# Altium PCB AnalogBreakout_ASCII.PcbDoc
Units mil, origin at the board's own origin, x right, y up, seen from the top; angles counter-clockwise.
Board outline 1000 x 3095 mil, 2 copper layers (Top Layer, Bottom Layer); 31 components, 26 nets, 117 pads, 10 vias.
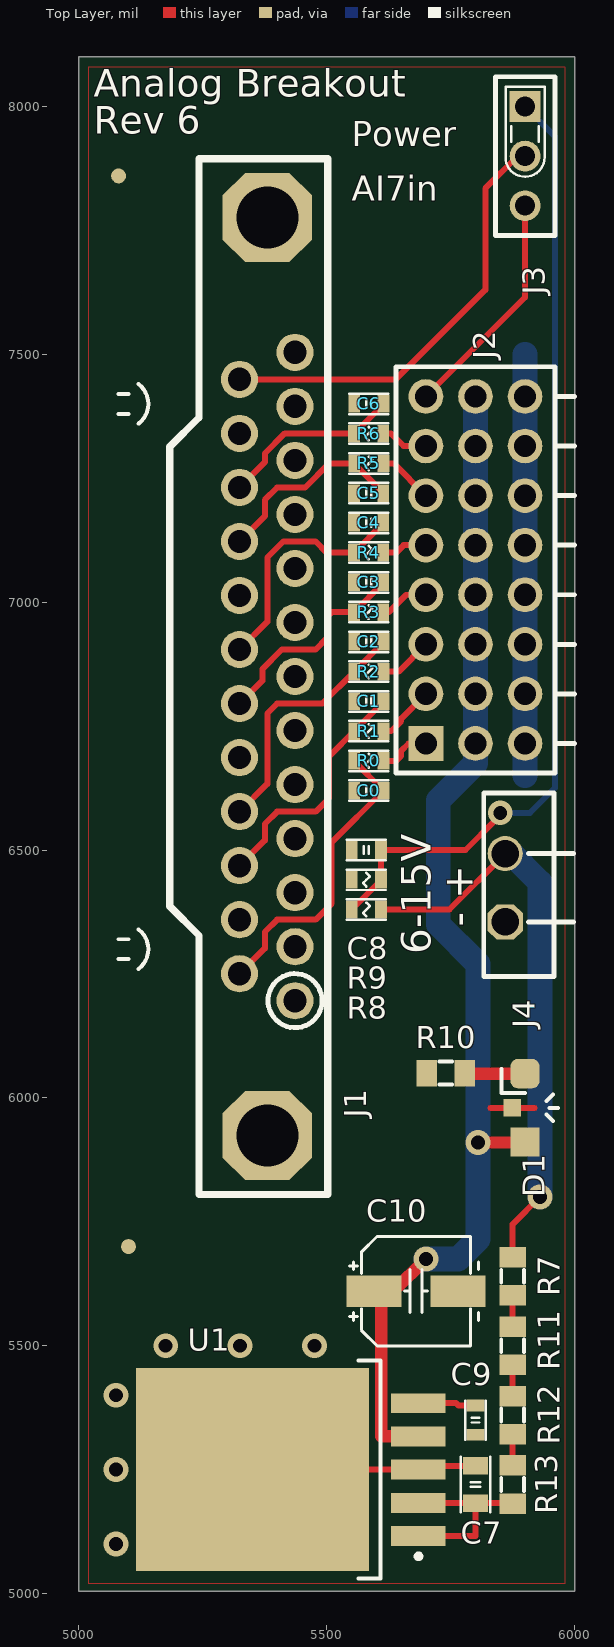
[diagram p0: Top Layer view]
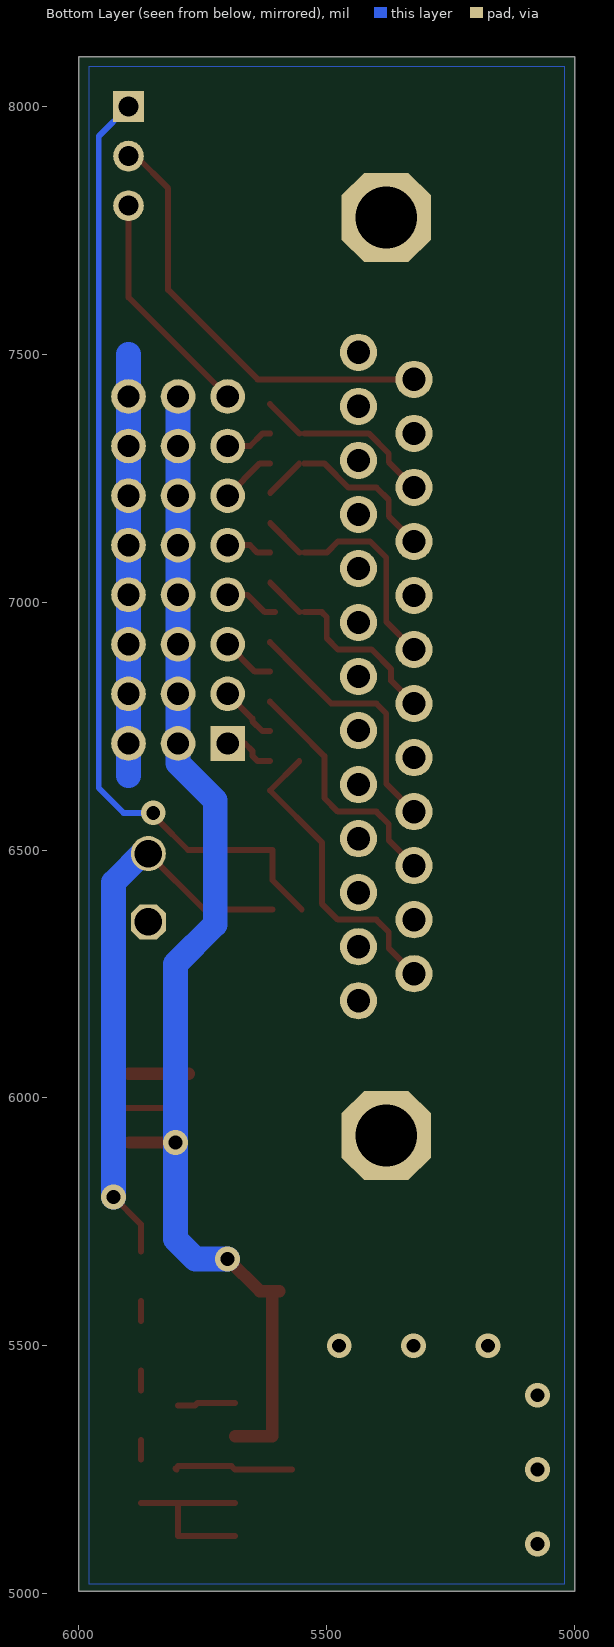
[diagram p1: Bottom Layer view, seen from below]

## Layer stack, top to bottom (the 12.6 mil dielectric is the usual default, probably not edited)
Top Layer: signal copper 1.4
Dielectric: dielectric 12.6, FR-4, Dk 4.8
Bottom Layer: signal copper 1.4

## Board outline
5000,8100 6000,8100 6000,5005 5000,5005

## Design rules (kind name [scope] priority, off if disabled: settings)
Clearance [All] p0: scope1count=1 scope1_0_kind=Board scope1_0_value=Board scope2count=1 scope2_0_kind=Board scope2_0_value=Board commentlength=0 gap=7
Clearance [All] p1: gap=7
ComponentClearance [All] p0: scope1count=1 scope1_0_kind=Board scope1_0_value=Board scope2count=1 scope2_0_kind=Board scope2_0_value=Board commentlength=0 gap=20 collisioncheckmode=3
ComponentClearance [All] p1: gap=20 collisioncheckmode=3 verticalgap=10 showdistances=FALSE
DiffPairsRouting [All] p0: scope1count=1 scope1_0_kind=Board scope1_0_value=Board scope2count=1 scope2_0_kind=Board scope2_0_value=Board commentlength=0
FanoutControl Fanout_BGA [All] p0 off: scope1count=1 scope1_0_kind=Board scope1_0_value=Board scope2count=1 scope2_0_kind=Board scope2_0_value=Board commentlength=69 // Protel DXP Scope 1 Expression Was: IsBGA   Fanout_BGA (Default Rule)
FanoutControl Fanout_LCC [All] p0 off: scope1count=1 scope1_0_kind=Board scope1_0_value=Board scope2count=1 scope2_0_kind=Board scope2_0_value=Board commentlength=69 // Protel DXP Scope 1 Expression Was: IsLCC   Fanout_LCC (Default Rule)
FanoutControl Fanout_SOIC [All] p0 off: scope1count=1 scope1_0_kind=Board scope1_0_value=Board scope2count=1 scope2_0_kind=Board scope2_0_value=Board commentlength=71 // Protel DXP Scope 1 Expression Was: IsSOIC   Fanout_SOIC (Default Rule)
FanoutControl Fanout_Small [All] p0 off: scope1count=1 scope1_0_kind=Board scope1_0_value=Board scope2count=1 scope2_0_kind=Board scope2_0_value=Board commentlength=84 // Protel DXP Scope 1 Expression Was: (CompPinCount < 5)   Fanout_Small (Default Rule)
FanoutControl Fanout_Default [All] p0: scope1count=1 scope1_0_kind=Board scope1_0_value=Board scope2count=1 scope2_0_kind=Board scope2_0_value=Board commentlength=30 // Fanout_Default (Default Rule)
Height [All] p0: scope1count=1 scope1_0_kind=Board scope1_0_value=Board scope2count=1 scope2_0_kind=Board scope2_0_value=Board commentlength=0
HoleSize [All] p0: scope1count=1 scope1_0_kind=Board scope1_0_value=Board scope2count=1 scope2_0_kind=Board scope2_0_value=Board commentlength=0 absolutevalues=TRUE maxlimit=150 minlimit=1 maxpercent=80.000 minpercent=20.000
HoleSize [All] p1: absolutevalues=TRUE maxlimit=150 minlimit=1 maxpercent=80.000 minpercent=20.000
LayerPairs [All] p0: scope1count=1 scope1_0_kind=Board scope1_0_value=Board scope2count=1 scope2_0_kind=Board scope2_0_value=Board commentlength=0 enforce=TRUE
PasteMaskExpansion [All] p0: scope1count=1 scope1_0_kind=Board scope1_0_value=Board scope2count=1 scope2_0_kind=Board scope2_0_value=Board commentlength=0 expansion=0
PlaneClearance [All] p0: scope1count=1 scope1_0_kind=Board scope1_0_value=Board scope2count=1 scope2_0_kind=Board scope2_0_value=Board commentlength=0 clearance=20
PlaneConnect [All] p0: scope1count=1 scope1_0_kind=Board scope1_0_value=Board scope2count=1 scope2_0_kind=Board scope2_0_value=Board commentlength=0 planeconnectstyle=Relief reliefexpansion=20 reliefentries=4 reliefconductorwidth=10 reliefairgap=10
PolygonConnect PolygonConnect_2 [All] p0 off: scope1count=1 scope1_0_kind=Board scope1_0_value=Board scope2count=1 scope2_0_kind=Board scope2_0_value=Board commentlength=46 connectstyle=Direct reliefconductorwidth=10 reliefentries=4 polygonreliefangle="90 Angle" // Protel DXP Scope 1 Expression Was: (IsVia)
PolygonConnect PolygonConnect_1 [All] p0 off: scope1count=1 scope1_0_kind=Board scope1_0_value=Board scope2count=1 scope2_0_kind=Board scope2_0_value=Board commentlength=58 connectstyle=Direct reliefconductorwidth=10 reliefentries=4 polygonreliefangle="90 Angle" // Protel DXP Scope 1 Expression Was: (InComponent('U1'))
PolygonConnect [All] p0: scope1count=1 scope1_0_kind=Board scope1_0_value=Board scope2count=1 scope2_0_kind=Board scope2_0_value=Board commentlength=0 connectstyle=Relief reliefconductorwidth=10 reliefentries=4 polygonreliefangle="90 Angle"
PolygonConnect PolygonConnect_2 [(IsVia)] p1: connectstyle=Direct reliefconductorwidth=10 reliefentries=4 polygonreliefangle="90 Angle"
PolygonConnect PolygonConnect_1 [(InComponent('U1'))] p2: connectstyle=Direct reliefconductorwidth=10 reliefentries=4 polygonreliefangle="90 Angle"
PolygonConnect [All] p3: connectstyle=Relief reliefconductorwidth=10 reliefentries=4 polygonreliefangle="90 Angle"
RoutingCorners [All] p0: scope1count=1 scope1_0_kind=Board scope1_0_value=Board scope2count=1 scope2_0_kind=Board scope2_0_value=Board commentlength=0 cornerstyle=45-Degree minsetback=100 maxsetback=100
RoutingLayers [All] p0: scope1count=1 scope1_0_kind=Board scope1_0_value=Board scope2count=1 scope2_0_kind=Board scope2_0_value=Board commentlength=0 top layer=Automatic bottom layer=Automatic
RoutingPriority [All] p0: scope1count=1 scope1_0_kind=Board scope1_0_value=Board scope2count=1 scope2_0_kind=Board scope2_0_value=Board commentlength=0
RoutingTopology [All] p0: scope1count=1 scope1_0_kind=Board scope1_0_value=Board scope2count=1 scope2_0_kind=Board scope2_0_value=Board commentlength=0 topology=Shortest
RoutingVias [All] p0: scope1count=1 scope1_0_kind=Board scope1_0_value=Board scope2count=1 scope2_0_kind=Board scope2_0_value=Board commentlength=0 holewidth=28 width=50 viastyle="Through Hole" minholewidth=28 minwidth=50 maxholewidth=50 maxwidth=80
RoutingVias [All] p1: holewidth=28 width=50 viastyle="Through Hole" minholewidth=28 minwidth=50 maxholewidth=50 maxwidth=80
ShortCircuit [All] p0: scope1count=1 scope1_0_kind=Board scope1_0_value=Board scope2count=1 scope2_0_kind=Board scope2_0_value=Board commentlength=0 allowed=FALSE
SolderMaskExpansion [All] p0: scope1count=1 scope1_0_kind=Board scope1_0_value=Board scope2count=1 scope2_0_kind=Board scope2_0_value=Board commentlength=0 expansion=4
SolderMaskExpansion [All] p1: expansion=4
TestPointUsage [All] p0: scope1count=1 scope1_0_kind=Board scope1_0_value=Board scope2count=1 scope2_0_kind=Board scope2_0_value=Board commentlength=0 valid=0 allowmultiple=FALSE
TestPointUsage [All] p1: valid=0 allowmultiple=FALSE
Testpoint [All] p0: scope1count=1 scope1_0_kind=Board scope1_0_value=Board scope2count=1 scope2_0_kind=Board scope2_0_value=Board commentlength=0 side=15 testpointundercomponent=TRUE minsize=40 maxsize=100 preferedsize=60 minholesize=0 maxholesize=40 preferedholesize=32 testpointgrid=1 style=1023 order=0123456789
Testpoint [All] p1: side=15 testpointundercomponent=TRUE minsize=40 maxsize=100 preferedsize=60 minholesize=0 maxholesize=40 preferedholesize=32 testpointgrid=1 style=1023 order=0123456789
UnRoutedNet [All] p0: scope1count=1 scope1_0_kind=Board scope1_0_value=Board scope2count=1 scope2_0_kind=Board scope2_0_value=Board commentlength=0
Width [All] p0: scope1count=1 scope1_0_kind=Board scope1_0_value=Board scope2count=1 scope2_0_kind=Board scope2_0_value=Board commentlength=0 maxlimit=100 minlimit=10 preferedwidth=10
Width [All] p1: maxlimit=100 minlimit=10 preferedwidth=10
17 further rules are at their usual default settings.

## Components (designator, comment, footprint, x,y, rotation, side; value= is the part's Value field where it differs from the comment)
C0 "1.0 uF 0603" C0603_C 5585,6620 r0 top
C1 "1.0 uF 0603" C0603_C 5585,6800 r0 top
C2 "1.0 uF 0603" C0603_C 5585,6920 r0 top
C3 "1.0 uF 0603" C0603_C 5584.53,7040 r0 top
C4 "1.0 uF 0603" C0603_C 5584.53,7160 r0 top
C5 "1.0 uF 0603" C0603_C 5584.53,7220 r0 top
C6 "1.0 uF 0603" C0603_C 5585,7400 r180 top
C7 "4.7uF 0805 25V X5R" C0805_C 5800,5220 r270 top
C8 "1.0 uF 0603" C0603_C 5580,6500 r0 top
C9 "1000 pF 0603" C0603_C 5800,5350 r90 top
C10 "22uF SMT 25V Elecrolytic" "SMT-CAN Panasonic C" 5680,5610 r90 top
D1 "LTST-S320GKT" "LED1208RA LITEON" 5900,5980 r0 top
J1 "DB25 Right Angle" "DB25 - RA" 5380,6850 r270 top
J2 "PWM_Header x8 RA" H100P3x8RA 5700,6715 r90 top
J3 "Jumper" J100P3 5900,8000 r270 top
J4 "3.5mm Mini Header RA" "WAGO 734-162" 5860,6355 r90 top
R0 "100 ohm 0603 1%" R0603_C 5585,6680 r0 top
R1 "100 ohm 0603 1%" R0603_C 5585,6740 r0 top
R2 "100 ohm 0603 1%" R0603_C 5585,6860 r0 top
R3 "100 ohm 0603 1%" R0603_C 5584.53,6980 r0 top
R4 "100 ohm 0603 1%" R0603_C 5584.53,7100 r0 top
R5 "100 ohm 0603 1%" R0603_C 5585,7280 r0 top
R6 "100 ohm 0603 1%" R0603_C 5584.53,7340 r0 top
R7 "1.00 ohm 0805 1%" R0805_M 5875,5640 r270 top
R8 "680 ohm 0805 1%" R0603_C 5580,6380 r0 top
R9 "1.0k ohm 0603 1%" R0603_C 5580,6440 r0 top
R10 "150 ohm 0805 1%" R0805_M 5740,6050 r0 top
R11 "1.00 ohm 0805 1%" R0805_M 5875,5500 r270 top
R12 "1.00 ohm 0805 1%" R0805_M 5875,5360 r270 top
R13 "1.00 ohm 0805 1%" R0805_M 5875,5220 r270 top
U1 "MIC5209-5.0BU" TO-263-5 5485,5250 r90 top

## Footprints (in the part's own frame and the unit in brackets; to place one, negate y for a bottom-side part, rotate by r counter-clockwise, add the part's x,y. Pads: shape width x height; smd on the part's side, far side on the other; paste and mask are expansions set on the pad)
C0603_C [mm]
  rect 0.6x0.9 smd: 1(-0.75,0) 2(0.75,0)
  silkscreen extent -1,-0.53 1,0.53
C0805_C [mm]
  rect 0.9x1.3 smd: 1(-0.95,0) 2(0.95,0)
  silkscreen extent -1.43,-0.76 1.43,0.76
"DB25 - RA" [mil]
  round 75 hole 47: 1(654.02,55.98) 2(545,56) 3(436,56) 4(327,56) 5(218,56) 6(109,56) 7(0,56) 8(-109,56) 9(-218,56) 10(-327,56) 11(-436,56) 12(-545,56) 13(-654.02,55.98) 14(599.49,-55.98) 15(490.5,-56) 16(381.5,-56) 17(272.5,-56) 18(163.5,-56) 19(54.5,-56) 20(-54.5,-56) 21(-163.5,-56) 22(-272.5,-56) 23(-381.5,-56) 24(-490.5,-56) 25(-599.49,-55.98)
  oct 180x180 hole 125: SHELL(-925.98,0) SHELL(925.98,0)
  silkscreen extent -1045,-197 1045,122
H100P3x8RA [mil] "Header 100mil, 8X2POS THRU RA"
  rect 70x70 hole 45: 1(0,0)
  round 70 hole 45: 2(0,-100) 3(0,-200) 4(100,0) 5(100,-100) 6(100,-200) 7(200,0) 8(200,-100) 9(200,-200) 10(300,0) 11(300,-100) 12(300,-200) 13(400,0) 14(400,-100) 15(400,-200) 16(500,0) 17(500,-100) 18(500,-200) 19(600,0) 20(600,-100) 21(600,-200) 22(700,0) 23(700,-100) 24(700,-200)
  silkscreen extent -60,-300 760,60
J100P3 [mil] "Selection Jumper 100mil, 3POS THRU VERT"
  rect 62x62 hole 40.16: 1(0,0)
  round 62 hole 40.16: 2(100,0) 3(200,0)
  silkscreen extent -60,-60 260,60
"LED1208RA LITEON" [mm] "Lite ON Side Fire 1208 LED"
  rect 1.5x1.5 smd: A(0,-1.75)
  rrect50% 1.5x1.5 smd: K(0,1.75)
  rect 0.9x0.9 smd: ""(-0.65,0)
  silkscreen extent -1.2,-0.67 1.7,2
R0603_C [mm]
  rect 0.6x0.9 smd: 1(-0.75,0) 2(0.75,0)
  silkscreen extent -1,-0.53 1,0.53
R0805_M [mm] "Chip Resistor, 2-Leads, Body 2.0x1.3mm, IPC Medium Density"
  rect 1.05x1.35 smd: 1(-0.975,0) 2(0.975,0)
  silkscreen extent -0.33,-0.58 0.33,0.58
"SMT-CAN Panasonic C" [mm] "Panasonic SMT-CAN type Capacitor, Size code C"
  rect 1.6x2.8 smd: +(0,2.15) -(0,-2.15)
  silkscreen extent -2.8,-3.2 2.8,3.4
TO-263-5 [mil] "TO-263-5"
  rect 40x110 smd: 1(-134,-200) 2(-67,-200) 3(0,-200) 4(67,-200) 5(134,-200)
  rect 410x470 smd: PAD(0,135)
  silkscreen extent -220,-205 220,-79
"WAGO 734-162" [mm] "3.5mm 10 A Protected Header RA"
  oct 1.8x1.8 hole 1.4: 1(0,0)
  round 1.8 hole 1.4: 2(3.5,0)
  silkscreen extent -2.8,-3.5 6.6,1.1

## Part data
C0 C1 C2 C3 C4 C5 C6: library part "0.22 uF 0603 10V", "Capacitor"
C7: "CERAMIC 4.7uF 25V X5R 0805"
C8: library part "0.1uF 0805 Bypass", "Capacitor"
C9: library part "1.0µF 0603 10V", "Capacitor"
D1: "Green 1208RA 20mA 2V 10mcd"
J1: library part "DB25 Female RA", "D-SUB RCPT RA 25POS PCB AU"
J2: "PWM Header x8 RA"
J3: library part "Jumper 3pos 100mil", "Selection Jumper"
J4: library part "WAGO 734-162", "3.5mm Header Protected against Mismating"
R0 R1 R2 R3 R4 R5 R6: library part "1.0k ohm 0603 1%", "1.0k ohm 0603 1%"
R7: library part "3.9 ohm 0603 1%", "3.9 ohm 0603 1%"
R8 R9: library part "1.0k ohm 0805 1%", "1.0k ohm 0805 1%"
R10: library part "51 ohm 0805 1%", "51 ohm 0805 1%"
R11 R12 R13: library part "2.00 ohm 0805 1%", "2.00 ohm 0805 1%"
U1: "5.0V 500mA Low-Noise LDO"

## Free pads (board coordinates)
  round 30 smd: 0(5080,7860) 0(5100,5700)

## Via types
v1: diameter 50, hole 28, Top Layer to Bottom Layer, 10 vias

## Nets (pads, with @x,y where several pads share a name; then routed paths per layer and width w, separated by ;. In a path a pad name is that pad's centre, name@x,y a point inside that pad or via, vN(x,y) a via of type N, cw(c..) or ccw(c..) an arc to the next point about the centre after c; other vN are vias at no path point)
5V: C10.+ D1.A J2.2 J2.5 J2.8 J2.11 J2.14 J2.17 J2.20 J2.23 U1.4 | length 2592.4
  Top Layer w25: C10.+ C10.+@5610,5610 ; U1.4 5610,5317 C10.+@5610,5610 ; v1(5700,5675) 5635,5610 C10.+@5610,5610 ; v1(5805,5910) D1.A@5898.9,5910
  Bottom Layer w50: v1(5700,5675) 5765,5675 5805,5715 v1(5805,5910) 5805,6270 ; J2.23 J2.20 J2.17 J2.14 J2.11 J2.8 J2.5 J2.2 5800,6675 5725,6600 5725,6350 ; 5725,6350 5805,6270 ; 5725,6350 5805,6270
AGND: C0.1 C1.1 C2.1 C3.1 C4.1 C5.1 C6.2 C7.1 C8.1 C9.1 C10.- J1.1 J1.3 J1.4 J1.6 J1.7 J1.9 J1.10 J1.12 J1.13 J2.3 J2.6 J2.9 J2.12 J2.15 J2.18 J2.21 J2.24 J4.1 R9.1 R10.1 U1.3 U1.PAD | length 1086.5
  Top Layer w12: U1.PAD@5570,5250 U1.3 5692.4,5257.4 C7.1 ; C7.1@5802.6,5250 C7.1@5805,5252.4
  Bottom Layer w50: 5900,6650 J2.3 J2.6 J2.9 J2.12 J2.15 J2.18 J2.21 J2.24 5900,7500
  other v1: 5075,5100 5075,5250 5075,5400 5175,5500 5325,5500 5475,5500
AI7: J1.25 J3.2 | length 882.7
  Top Layer w12: J1.25 5639.49,7449.49 5820,7630 5820,7835 5885,7900 J3.2
ANALOGINPUT0: J2.1 R0.2 | length 106.3
  Top Layer w12: R0.2 5640,6680 5650,6690 5650,6700 5665,6715 J2.1 J2.1@5699.53,6715
ANALOGINPUT1: J2.4 R1.2 | length 119.5
  Top Layer w12: R1.2 5630,6740 5650,6760 5650,6765 J2.4
ANALOGINPUT2: J2.7 R2.2 | length 108.3
  Top Layer w12: R2.2 5645,6860 J2.7
ANALOGINPUT3: J2.10 R3.2 | length 110.4
  Top Layer w12: R3.2@5604.06,6980 R3.2 5625,6980 5660,7015 J2.10
ANALOGINPUT4: J2.13 R4.2 | length 92.2
  Top Layer w12: R4.2 5640,7100 5655,7115 J2.13
ANALOGINPUT5: J2.16 R5.2 | length 112.4
  Top Layer w12: R5.2 5635,7280 J2.16
ANALOGINPUT6: J2.19 R6.2 | length 96.3
  Top Layer w12: R6.2 5630,7340 5655,7315 J2.19
ANALOGINPUT7: J2.22 J3.3 | length 467.8
  Top Layer w12: J2.22 5900,7615 J3.3
NetC0_2: C0.2 J1.14 R0.1 | length 619.7
  Top Layer w12: J1.14 5375,6301.5 5375,6334.47 5400,6359.47 5477.53,6359.47 5510,6391.94 5510,6515.47 C0.2 5555.47,6679.06 R0.1
NetC1_2: C1.2 J1.16 R1.1 | length 497.3
  Top Layer w12: J1.16 5375,6519.5 5375,6552.47 5400,6577.47 5477.53,6577.47 5505,6604.94 5505,6689.53 R1.1 5614.53,6799.06 C1.2
NetC2_2: C2.2 J1.17 R2.1 | length 516.1
  Top Layer w12: J1.17 5380,6633.5 5380,6775.47 5400,6795.47 5490.94,6795.47 R2.1 5614.53,6919.06 C2.2
NetC3_2: C3.2 J1.19 R3.1 | length 420.9
  Top Layer w12: J1.19 5370,6841.5 5370,6865 5409.47,6904.47 5477.53,6904.47 5500,6926.94 5500,6970 5510,6980 R3.1@5545,6980 ; R3.1 5614.06,7039.06 C3.2
NetC4_2: C4.2 J1.20 R4.1 | length 480.9
  Top Layer w12: J1.20 5380,6960.5 5380,7090 5412.47,7122.47 5477.53,7122.47 5500,7100 R4.1@5545,7100 ; R4.1 5614.06,7159.06 C4.2
NetC5_2: C5.2 J1.22 R5.1 | length 390.3
  Top Layer w12: J1.22 5375,7173.5 5375,7206.47 5400,7231.47 5456.47,7231.47 5505,7280 R5.1@5545.47,7280 ; R5.1 5555.47,7279.53 5614.06,7220.94 C5.2
NetC6_1: C6.1 J1.23 R6.1 | length 361.2
  Top Layer w12: J1.23 5375,7282.5 5375,7300 5415.47,7340.47 5500,7340.47 5500.47,7340 R6.1@5545,7340 ; R6.1 5614.53,7399.53 C6.1
NetC7_2: C7.2 R13.2 U1.1 U1.2 | length 372
  Top Layer w12: U1.1 5800,5116 C7.2 ; U1.2 5685,5182.6 C7.2 ; R13.2@5875,5182.6 C7.2
NetC8_2: C8.2 J3.1 R8.1 R9.2 | length 1985.9
  Top Layer w12: R8.1 5609.53,6439.06 R9.2 C8.2 5780,6500 v1@5840,6560 ; J3.1@5881.61,8000 J3.1 ; v1@5840,6560 5850,6570 v1(5850,6575) v1@5840,6560
  Bottom Layer w12: v1(5850,6575) 5910,6575 5960,6625 5960,7940 J3.1
NetC9_2: C9.2 U1.5 | length 116.9
  Top Layer w12: U1.5 5761,5384 5765.47,5379.53 C9.2
NetD1_K: D1.K R10.2 | length 121.6
  Top Layer w25: R10.2@5778.39,6048.9 D1.K
NetR7_2: R7.2 R11.1 | length 40
  Top Layer w12: R11.1@5875,5550 R7.2@5875,5590
NetR11_2: R11.2 R12.1 | length 40
  Top Layer w12: R12.1@5875,5410 R11.2@5875,5450
NetR12_2: R12.2 R13.1 | length 40
  Top Layer w12: R13.1@5875,5270 R12.2@5875,5310
VBATT: J4.2 R7.1 R8.2 | length 1156.9
  Top Layer w12: R8.2 5747.2,6380 J4.2 ; R7.1@5875,5690 5875,5745 v1(5930,5800)
  Bottom Layer w50: J4.2@5865,6500 5866.1,6498.9 5930,6435 v1(5930,5800)
pads on no net: D1. J1.2 J1.5 J1.8 J1.11 J1.15 J1.18 J1.21 J1.24 J1.SHELL
copper on no net: | length 88.8
  Top Layer w12: 5830,5980 5874.41,5980 5918.82,5980

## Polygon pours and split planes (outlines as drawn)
AGND on Top Layer "GND" (solid, pour order 1000): 5020,8080 5980,8080 5980,5020 5020,5020 5020,8080
AGND on Bottom Layer "PWR" (solid, remove dead copper, pour order 1001): 5020,8080 5980,8080 5980,5020 5020,5020 5020,8080

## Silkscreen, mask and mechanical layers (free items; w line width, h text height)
Top Overlay:
  lines w8: 5080,6280 5100,6280 ; 5080,6320 5100,6320 ; 5080,7380 5100,7380 ; 5080,7420 5100,7420 ; 5120,6260 ccw(c5090,6300) 5120,6340 ; 5120,7360 ccw(c5090,7400) 5120,7440
  text "Analog Breakout" at 5030,8020 h55
  text "Rev 6" at 5030,7945 h55
  text "Power" at 5550,7920 h50
  text "AI7in" at 5550,7810 h50
  text "- +" at 5795,6345 h60 r90
  text "6-15V" at 5710,6290 h60 r90
Mechanical 1:
  lines w1.67: 7306.66,7663.72 11192.83,7663.72 ; 8941.72,6281.72 8941.72,7650.39
  lines w10: 5000,5005 6000,5005 6000,8100 5000,8100 5000,5005
  text "P" at 7651.32,8715.91 h148.77
  text "r" at 7743.01,8715.91 h148.77
  text "o" at 7789.69,8715.91 h148.77
  text "j" at 7866.37,8715.91 h148.77
  text "e" at 7898.05,8715.91 h148.77
  text "c" at 7974.73,8715.91 h148.77
  text "t" at 8044.75,8715.91 h148.77
  text "P" at 8843.48,8715.91 h148.77
  text "h" at 8935.17,8715.91 h148.77
  text "o" at 9011.85,8715.91 h148.77
  text "e" at 9088.54,8715.91 h148.77
  text "n" at 9165.23,8715.91 h148.77
  text "i" at 9241.91,8715.91 h148.77
  text "x" at 9271.92,8715.91 h148.77
  text "B" at 7651.32,8544.2 h148.77
  text "o" at 7743.01,8544.2 h148.77
  text "a" at 7819.7,8544.2 h148.77
  text "r" at 7896.38,8544.2 h148.77
  text "d" at 7943.06,8544.2 h148.77
  text "A" at 8843.48,8544.2 h148.77
  text "n" at 8935.17,8544.2 h148.77
  text "a" at 9011.85,8544.2 h148.77
  text "l" at 9088.54,8544.2 h148.77
  text "o" at 9118.55,8544.2 h148.77
  text "g" at 9195.23,8544.2 h148.77
  text "B" at 9310.26,8544.2 h148.77
  text "r" at 9401.95,8544.2 h148.77
  text "e" at 9448.63,8544.2 h148.77
  text "a" at 9525.31,8544.2 h148.77
  text "k" at 9602,8544.2 h148.77
  text "o" at 9673.68,8544.2 h148.77
  text "u" at 9750.37,8544.2 h148.77
  text "t" at 9827.05,8544.2 h148.77
  text "R" at 7651.32,8372.5 h148.77
  text "e" at 7751.35,8372.5 h148.77
  text "v" at 7828.03,8372.5 h148.77
  text "6" at 8843.48,8372.5 h148.77
  text "E" at 7651.32,8200.79 h148.77
  text "n" at 7743.01,8200.79 h148.77
  text "g" at 7819.7,8200.79 h148.77
  text "i" at 7896.38,8200.79 h148.77
  text "n" at 7926.39,8200.79 h148.77
  text "e" at 8003.07,8200.79 h148.77
  text "e" at 8079.76,8200.79 h148.77
  text "r" at 8156.44,8200.79 h148.77
  text "E" at 8843.48,8200.79 h148.77
  text "r" at 8935.17,8200.79 h148.77
  text "i" at 8981.85,8200.79 h148.77
  text "c" at 9011.85,8200.79 h148.77
  text "V" at 9120.21,8200.79 h148.77
  text "a" at 9211.9,8200.79 h148.77
  text "n" at 9288.59,8200.79 h148.77
  text "W" at 9365.27,8200.79 h148.77
  text "y" at 9503.64,8200.79 h148.77
  text "k" at 9568.66,8200.79 h148.77
  text "R" at 8843.48,8032.41 h148.77
  text "u" at 8943.5,8032.41 h148.77
  text "s" at 9020.19,8032.41 h148.77
  text "s" at 9090.21,8032.41 h148.77
  text "B" at 9198.57,8032.41 h148.77
  text "e" at 9290.26,8032.41 h148.77
  text "a" at 9366.94,8032.41 h148.77
  text "v" at 9443.63,8032.41 h148.77
  text "i" at 9511.98,8032.41 h148.77
  text "s" at 9541.98,8032.41 h148.77
  text "C" at 7333.3,7695.21 h148.77
  text "o" at 7433.33,7695.21 h148.77
  text "n" at 7510.01,7695.21 h148.77
  text "s" at 7586.7,7695.21 h148.77
  text "t" at 7656.71,7695.21 h148.77
  text "r" at 7695.06,7695.21 h148.77
  text "u" at 7741.73,7695.21 h148.77
  text "c" at 7818.42,7695.21 h148.77
  text "t" at 7888.44,7695.21 h148.77
  text "i" at 7926.78,7695.21 h148.77
  text "o" at 7956.79,7695.21 h148.77
  text "n" at 8033.47,7695.21 h148.77
  text "L" at 7333.3,7523.5 h148.77
  text "a" at 7409.99,7523.5 h148.77
  text "y" at 7486.67,7523.5 h148.77
  text "e" at 7551.69,7523.5 h148.77
  text "r" at 7628.37,7523.5 h148.77
  text "s" at 7675.05,7523.5 h148.77
  text "2" at 8975.02,7523.5 h148.77
  text "F" at 7333.3,7351.79 h148.77
  text "i" at 7418.32,7351.79 h148.77
  text "n" at 7448.33,7351.79 h148.77
  text "i" at 7525.01,7351.79 h148.77
  text "s" at 7555.02,7351.79 h148.77
  text "h" at 7625.04,7351.79 h148.77
  text "e" at 7701.72,7351.79 h148.77
  text "d" at 7778.41,7351.79 h148.77
  text "T" at 7893.44,7351.79 h148.77
  text "h" at 7980.13,7351.79 h148.77
  text "i" at 8056.81,7351.79 h148.77
  text "c" at 8086.82,7351.79 h148.77
  text "k" at 8156.84,7351.79 h148.77
  text "n" at 8228.52,7351.79 h148.77
  text "e" at 8305.21,7351.79 h148.77
  text "s" at 8381.89,7351.79 h148.77
  text "s" at 8451.91,7351.79 h148.77
  text "0" at 8975.02,7351.79 h148.77
  text "6" at 9051.7,7351.79 h148.77
  text "3" at 9128.39,7351.79 h148.77
  text "+" at 9243.42,7351.79 h148.77
  text "/" at 9323.44,7351.79 h148.77
  text "-" at 9361.78,7351.79 h148.77
  text "3" at 9446.8,7351.79 h148.77
  text "0" at 9523.48,7351.79 h148.77
  text "%" at 9600.17,7351.79 h148.77
  text "S" at 7333.3,7180.08 h148.77
  text "o" at 7424.99,7180.08 h148.77
  text "l" at 7501.68,7180.08 h148.77
  text "d" at 7531.68,7180.08 h148.77
  text "e" at 7608.37,7180.08 h148.77
  text "r" at 7685.05,7180.08 h148.77
  text "M" at 7770.07,7180.08 h148.77
  text "a" at 7885.1,7180.08 h148.77
  text "s" at 7961.79,7180.08 h148.77
  text "k" at 8031.81,7180.08 h148.77
  text "B" at 8975.02,7180.08 h148.77
  text "l" at 9066.71,7180.08 h148.77
  text "u" at 9096.71,7180.08 h148.77
  text "e" at 9173.4,7180.08 h148.77
  text "T" at 8975.02,7008.37 h148.77
  text "o" at 9061.7,7008.37 h148.77
  text "p" at 9138.39,7008.37 h148.77
  text "&" at 9253.42,7008.37 h148.77
  text "B" at 9383.45,7008.37 h148.77
  text "o" at 9475.14,7008.37 h148.77
  text "t" at 9551.83,7008.37 h148.77
  text "t" at 9590.17,7008.37 h148.77
  text "o" at 9628.51,7008.37 h148.77
  text "m" at 9705.2,7008.37 h148.77
  text "S" at 7333.3,6836.66 h148.77
  text "i" at 7424.99,6836.66 h148.77
  text "l" at 7455,6836.66 h148.77
  text "k" at 7485,6836.66 h148.77
  text "S" at 7595.03,6836.66 h148.77
  text "c" at 7686.72,6836.66 h148.77
  text "r" at 7756.74,6836.66 h148.77
  text "e" at 7803.42,6836.66 h148.77
  text "e" at 7880.1,6836.66 h148.77
  text "n" at 7956.79,6836.66 h148.77
  text "U" at 8975.02,6836.66 h148.77
  text "n" at 9075.04,6836.66 h148.77
  text "s" at 9151.73,6836.66 h148.77
  text "p" at 9221.74,6836.66 h148.77
  text "e" at 9298.43,6836.66 h148.77
  text "c" at 9375.11,6836.66 h148.77
  text "i" at 9445.13,6836.66 h148.77
  text "f" at 9475.14,6836.66 h148.77
  text "i" at 9515.15,6836.66 h148.77
  text "e" at 9545.16,6836.66 h148.77
  text "d" at 9621.84,6836.66 h148.77
  text "C" at 9736.87,6836.66 h148.77
  text "o" at 9836.9,6836.66 h148.77
  text "l" at 9913.58,6836.66 h148.77
  text "o" at 9943.59,6836.66 h148.77
  text "r" at 10020.27,6836.66 h148.77
  text "T" at 8975.02,6664.95 h148.77
  text "o" at 9061.7,6664.95 h148.77
  text "p" at 9138.39,6664.95 h148.77
  text "O" at 9253.42,6664.95 h148.77
  text "n" at 9361.78,6664.95 h148.77
  text "l" at 9438.46,6664.95 h148.77
  text "y" at 9468.47,6664.95 h148.77
  text "C" at 7333.3,6493.24 h148.77
  text "o" at 7433.33,6493.24 h148.77
  text "p" at 7510.01,6493.24 h148.77
  text "p" at 7586.7,6493.24 h148.77
  text "e" at 7663.38,6493.24 h148.77
  text "r" at 7740.07,6493.24 h148.77
  text "W" at 7825.09,6493.24 h148.77
  text "e" at 7963.46,6493.24 h148.77
  text "i" at 8040.14,6493.24 h148.77
  text "g" at 8070.15,6493.24 h148.77
  text "h" at 8146.83,6493.24 h148.77
  text "t" at 8223.52,6493.24 h148.77
  text "1" at 8975.02,6493.24 h148.77
  text "/" at 9051.7,6493.24 h148.77
  text "2" at 9090.04,6493.24 h148.77
  text "o" at 9205.07,6493.24 h148.77
  text "z" at 9281.76,6493.24 h148.77
  text "o" at 9386.78,6493.24 h148.77
  text "r" at 9463.47,6493.24 h148.77
  text "t" at 9548.49,6493.24 h148.77
  text "h" at 9586.83,6493.24 h148.77
  text "i" at 9663.52,6493.24 h148.77
  text "c" at 9693.53,6493.24 h148.77
  text "k" at 9763.54,6493.24 h148.77
  text "e" at 9835.23,6493.24 h148.77
  text "r" at 9911.91,6493.24 h148.77
  text "S" at 7333.3,6321.54 h148.77
  text "p" at 7424.99,6321.54 h148.77
  text "e" at 7501.68,6321.54 h148.77
  text "c" at 7578.36,6321.54 h148.77
  text "i" at 7648.38,6321.54 h148.77
  text "a" at 7678.39,6321.54 h148.77
  text "l" at 7755.07,6321.54 h148.77
  text "C" at 8975.02,6321.54 h148.77
  text "o" at 9075.04,6321.54 h148.77
  text "n" at 9151.73,6321.54 h148.77
  text "f" at 9228.41,6321.54 h148.77
  text "o" at 9268.42,6321.54 h148.77
  text "r" at 9345.11,6321.54 h148.77
  text "m" at 9391.79,6321.54 h148.77
  text "a" at 9510.15,6321.54 h148.77
  text "l" at 9586.83,6321.54 h148.77
  text "C" at 9655.18,6321.54 h148.77
  text "o" at 9755.21,6321.54 h148.77
  text "a" at 9831.89,6321.54 h148.77
  text "t" at 9908.58,6321.54 h148.77
  text "P" at 9985.26,6321.54 h148.77
  text "e" at 10076.95,6321.54 h148.77
  text "r" at 10153.64,6321.54 h148.77
  text "M" at 10238.66,6321.54 h148.77
  text "e" at 10353.69,6321.54 h148.77
  text "c" at 10430.37,6321.54 h148.77
  text "h" at 10500.39,6321.54 h148.77
  text "a" at 10577.08,6321.54 h148.77
  text "n" at 10653.76,6321.54 h148.77
  text "i" at 10730.45,6321.54 h148.77
  text "c" at 10760.46,6321.54 h148.77
  text "a" at 10830.47,6321.54 h148.77
  text "l" at 10907.16,6321.54 h148.77
  text "6" at 10975.51,6321.54 h148.77
Mechanical 6:
  lines w15: 4920,5860 5020,5960 ; 4920,5960 4820,5860 6320,5860 6420,5960 ; 5020,5860 5120,5960 ; 5120,5860 5220,5960 ; 5220,5860 5320,5960 ; 5320,5860 5420,5960 ; 5420,5860 5520,5960 ; 5520,5860 5620,5960 ; 5620,5860 5720,5960 ; 5720,5860 5820,5960 ; 5820,5860 5920,5960 ; 5920,5860 6020,5960 ; 6020,5860 6120,5960 ; 6120,5860 6220,5960 ; 6220,5860 6320,5960
  text "Conformal Coat Top" at 6100,5700 h60
  text "Below This Line" at 6100,5600 h60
